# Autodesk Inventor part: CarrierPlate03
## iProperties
Created: 2008-02
Part Number: CarrierPlate03
Document SubType Name: Modeling
Designer: grh
Density: 1 g/cm^3
Author: grh
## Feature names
1. Extrusion1
